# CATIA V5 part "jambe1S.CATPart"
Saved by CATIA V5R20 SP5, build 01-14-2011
Part number: jambe1S
Publications: "Plan.1", "Droite.1", "Droite.2", "Point.2", "Plan.3", "Plan.2", "V", "H", "Droite.3", "Point.3", "Point.4", "Droite.4", "Plan.4", "Droite.5"
Bounding box of the stored display mesh (mm): x 0 to 400, y -1070 to -70, z 10 to 50
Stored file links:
  U:\think motion\fin\jambe1S.CATPart
  U:\think motion\fin\squelette.CATProduct
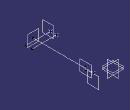
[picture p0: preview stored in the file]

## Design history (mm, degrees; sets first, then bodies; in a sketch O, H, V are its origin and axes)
External parameters (linked from other documents)
  `External.écartement jambe` = 650 mm
  `External.longueur jambe` = 1000 mm
  `External.implentation verin2` = 130 mm
Set1
  Point1: linked copy from another document
Set2
  Plane1: type Offset, RefPlane yz-plane, Offset 325 {= `External.écartement jambe` /2}
  Line1: type PtDir, RefPoint Point1, Direction (0, 1, 0), Start 0, End 1000 {= `External.longueur jambe`}
  Plane2: type Normal, Curve Line1, RefPoint vertex of Line1
  Plane3: type Angle, RefPlane Plane2, Direction Z axis, Angle 90
  Point2: type OnPlane, Support Plane3, RefPoint vertex of Line1, H -35, V -14, Direction (0, -1, 0)
  Line2: type PtDir, RefPoint Point2, Direction Plane3, Start 0, End 400
  Point3: type OnPlane, Support Plane3, RefPoint vertex of Line1, H -135, V -14 {= Point2.V}, Direction (0, -1, 0)
  Line3: type PtDir, RefPoint Point3, Direction Plane3, Start 0, End 400
  Point4: type OnCurve, Support Line1, RefPoint Point1, Length 130 {= `External.implentation verin2`}
  Line4: type PtDir, RefPoint Point4, Direction Plane1, Start 0, End 5
  Plane4: type Normal, Curve Line4, RefPoint Point4
  Line5: type PtDir, RefPoint Point4, Direction Plane5, Start -20, End 20
  Plane5: stored without definition
Body1 (main body)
